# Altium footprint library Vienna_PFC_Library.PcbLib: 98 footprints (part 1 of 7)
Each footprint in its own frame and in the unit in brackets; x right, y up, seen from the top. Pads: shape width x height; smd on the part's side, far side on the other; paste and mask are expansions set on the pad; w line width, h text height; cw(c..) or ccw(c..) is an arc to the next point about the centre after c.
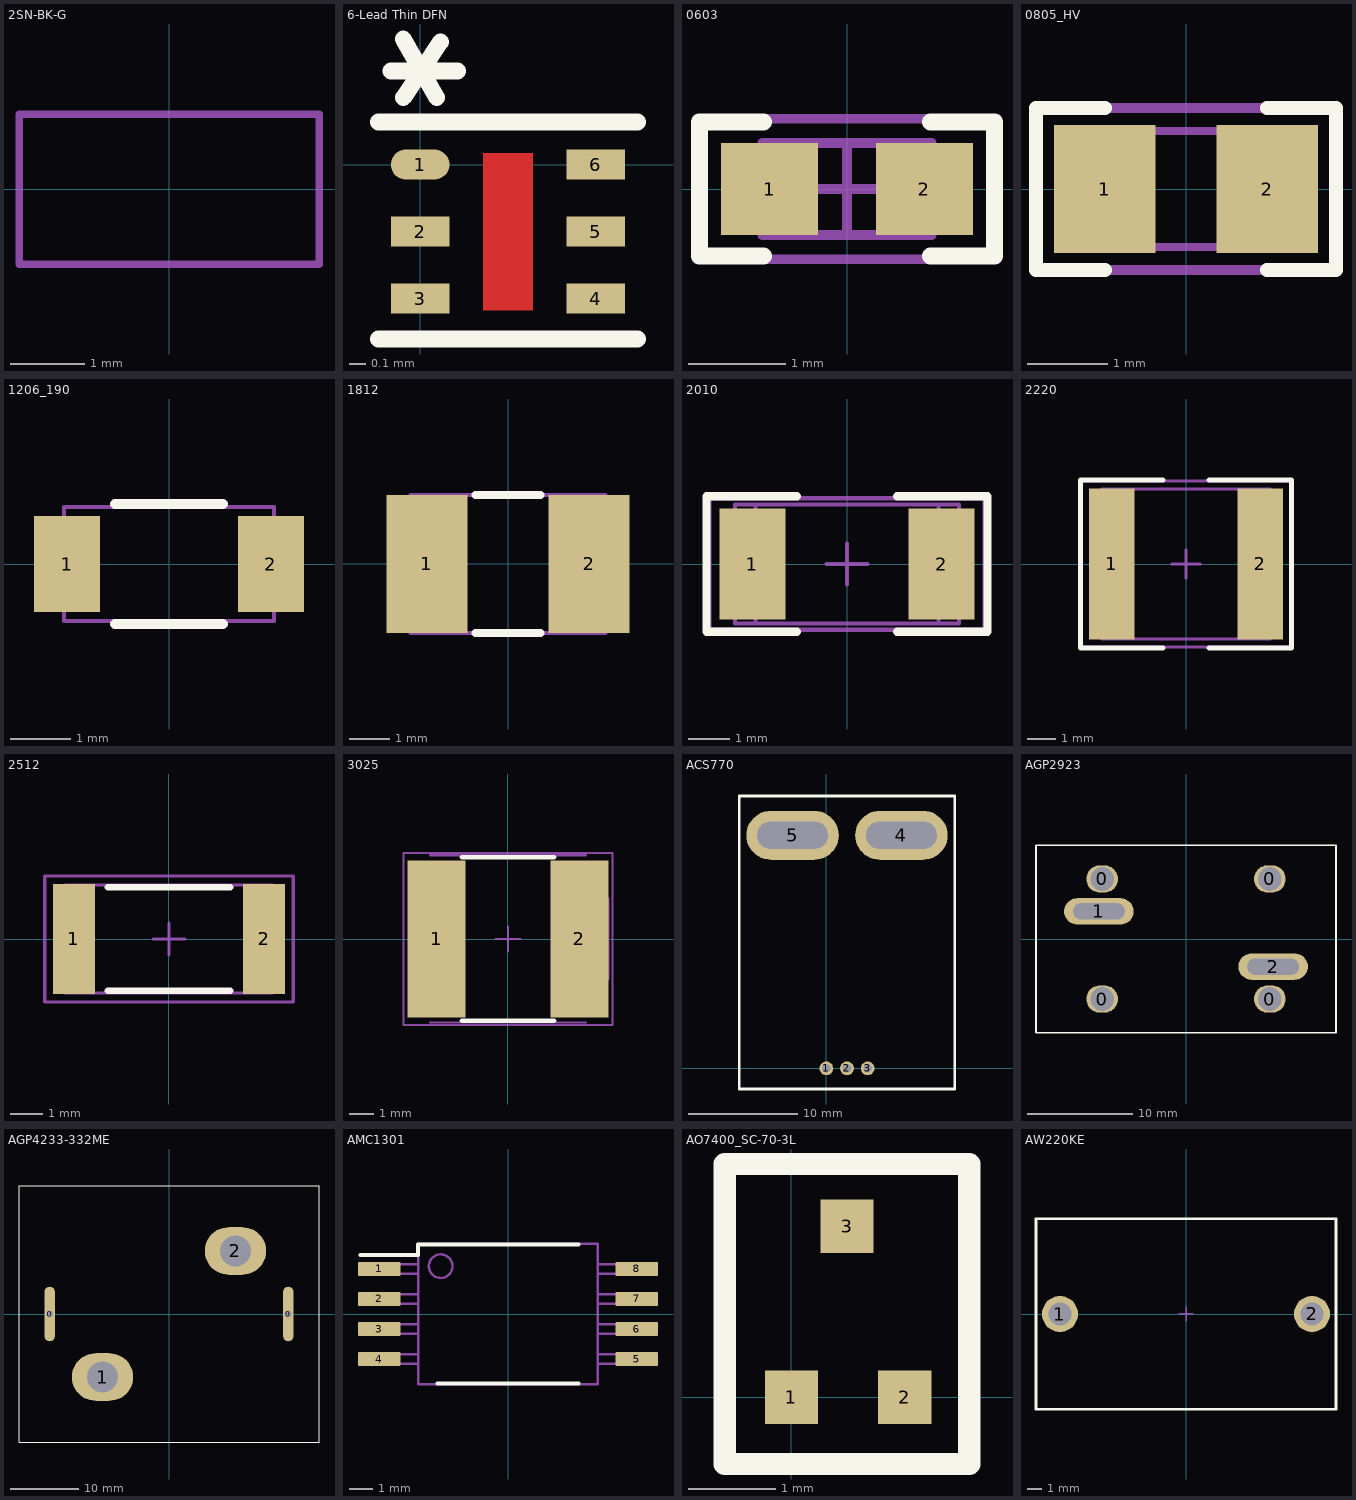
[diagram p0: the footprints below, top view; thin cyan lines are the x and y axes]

## 2SN-BK-G [mil] "Samtec STEP model"
height 345
pads (1):
  round 1 on Mech3: 0(0,0)
Mechanical 5:
  lines w4: -80,-40 80,-40 80,40 -80,40 -80,-40
3D body "2SN-BK-X-BASIC.stp": height 187.5, standoff 12.5, extent -78.5,-39.2 78.5,39.2

## 6-Lead Thin DFN [mm]
height 0.55
pads (6):
  oval 0.35x0.18 smd: 1(0,0)
  rect 0.35x0.18 smd: 2(0,-0.4) 3(0,-0.8) 4(1.05,-0.8) 5(1.05,-0.4) 6(1.05,0)
Top Layer:
  rectangle: 0.375,-0.87 0.675,0.07
Top Overlay:
  lines w0.1: -0.25,-1.041 1.3,-1.041 ; -0.25,0.254 1.3,0.254 ; -0.175,0.559 0.225,0.559 ; -0.1,0.4 0.122,0.733 ; -0.1,0.75 0.1,0.4

## 0603 [mm] "0603 from SM-752 data"
height 1
pads (2):
  rect 1x0.95 smd: 1(-0.8,0) 2(0.8,0)
Top Overlay:
  lines w0.178: -0.864,-0.691 -1.524,-0.691 -1.524,0.693 -0.864,0.693 ; 0.864,-0.691 1.524,-0.691 1.524,0.693 0.864,0.693
Mechanical 5:
  lines w0.1: -1.55,-0.725 -1.55,0.725 1.55,0.725 1.55,-0.725 -1.55,-0.725
Mechanical 13:
  lines w0.1: -0.55,-0.475 -0.55,0.475 ; 0.55,-0.475 0.55,0.475 ; -0.875,-0.475 0.875,-0.475 0.875,0.475 -0.875,0.475 -0.875,-0.475
Mechanical 15:
  lines w0.1: -0.475,0 0.475,0 ; 0,-0.475 0,0.475 ; -1.55,-0.725 1.55,-0.725 1.55,0.725 -1.55,0.725 -1.55,-0.725
3D body: height 1, standoff 0, extent -0.874,-0.474 -0.551,0.474
3D body: height 1, standoff 0, extent -0.549,-0.474 0.549,0.474
3D body: height 1, standoff 0, extent 0.551,-0.474 0.874,0.474

## 0805_HV [mil] "0805 with 30mil clearance between pads"
height 57.09
pads (2):
  rect 50x63 smd: 1(-40,0) 2(40,0)
Top Overlay:
  lines w7: -40,-40 -74,-40 -74,0 -74,40 -40,40 ; 40,-40 74,-40 74,0 74,40 40,40
Mechanical 5:
  lines w5: -74,-40 74,-40 74,40 -74,40 -74,-40
Mechanical 13:
  lines w3.94: -25.59,-28.54 -25.59,28.54 ; 25.59,-28.54 25.59,28.54 ; -43.31,-28.54 43.31,-28.54 43.31,28.54 -43.31,28.54 -43.31,-28.54
3D body: height 57.09, standoff 0, extent -43.29,-28.52 -25.61,28.52
3D body: height 57.09, standoff 0, extent -25.57,-28.52 25.57,28.52
3D body: height 57.09, standoff 0, extent 25.61,-28.52 43.29,28.52

## 1206_190 [mm] "1206_190"
height 1.9
pads (2):
  rect 1.1x1.6 smd: 1(-1.7,0) 2(1.7,0)
Top Overlay:
  lines w0.17: -0.9,-1 0.9,-1 ; -0.9,1 0.9,1
Mechanical 5:
  lines w0.07: -1.75,-0.95 -1.75,0.95 1.75,0.95 1.75,-0.95 -1.75,-0.95
3D body: height 1.9, standoff 0, extent 1.301,-0.949 1.749,0.949
3D body: height 1.9, standoff 0, extent -1.299,-0.949 1.299,0.949
3D body: height 1.9, standoff 0, extent -1.749,-0.949 -1.301,0.949

## 1812 [mm] "SMD, 2-Leads, Body 4.8x3.4mm"
height 2.54
pads (2):
  rect 2x3.4 smd: 1(-2,0) 2(2,0)
Top Overlay:
  lines w0.2: -0.8,-1.7 0.8,-1.7 ; -0.8,1.7 0.8,1.7
Mechanical 5:
  lines w0.1: -1.9,-1.7 -1.9,1.7 ; 1.9,-1.7 1.9,1.7 ; -2.4,-1.7 2.4,-1.7 2.4,1.7 -2.4,1.7 -2.4,-1.7
  text ".Designator" at -1.875,-0.5 h1.02
3D body: height 2.54, standoff 0, extent -2.399,-1.699 -1.901,1.699
3D body: height 2.54, standoff 0, extent -1.899,-1.699 1.899,1.699
3D body: height 2.54, standoff 0, extent 1.901,-1.699 2.399,1.699

## 2010 [mm] "Chip Capacitor, Body 5.08x2.54mm, IPC Medium Density"
height 1.66
pads (2):
  rect 1.6x2.7 smd: 1(-2.3,0) 2(2.3,0)
Top Overlay:
  lines w0.2: -1.219,-1.65 -3.419,-1.65 -3.419,1.65 -1.219,1.65 ; 1.219,-1.65 3.419,-1.65 3.419,1.65 1.219,1.65
Mechanical 5:
  lines w0.1: -2.73,-1.45 2.73,-1.45 2.73,1.45 -2.73,1.45 -2.73,-1.45
Mechanical 13:
  lines w0.1: -2.23,-1.45 -2.23,1.45 ; 2.23,-1.45 2.23,1.45 ; -2.73,-1.45 -2.73,1.45 2.73,1.45 2.73,-1.45 -2.73,-1.45
Mechanical 15:
  lines w0.1: -0.5,0 0.5,0 ; 0,-0.5 0,0.5 ; -3.35,-1.6 -3.35,1.6 3.35,1.6 3.35,-1.6 -3.35,-1.6
3D body: height 1.66, standoff 0, extent 2.231,-1.449 2.729,1.449
3D body: height 1.66, standoff 0, extent -2.229,-1.449 2.229,1.449
3D body: height 1.66, standoff 0, extent -2.729,-1.449 -2.231,1.449

## 2220 [mm] "Chip Capacitor, Body 5.7x5.0mm, IPC Medium Density"
height 2.8
pads (2):
  rect 1.6x5.3 smd: 1(-2.6,0) 2(2.6,0)
Top Overlay:
  lines w0.178: -0.811,-2.939 -3.693,-2.939 -3.693,2.939 -0.811,2.939 ; 0.811,-2.939 3.693,-2.939 3.693,2.939 0.811,2.939
Mechanical 5:
  lines w0.1: -2.95,-2.625 -2.95,2.625 2.95,2.625 2.95,-2.625 -2.95,-2.625
  text ".Designator" at -1.875,-0.5 h1.02
Mechanical 13:
  lines w0.1: -2.75,-2.625 -2.75,2.625 ; 2.75,-2.625 2.75,2.625 ; -2.95,-2.625 2.95,-2.625 2.95,2.625 -2.95,2.625 -2.95,-2.625
Mechanical 15:
  lines w0.1: -0.5,0 0.5,0 ; 0,-0.5 0,0.5 ; -3.65,-2.9 3.65,-2.9 3.65,2.9 -3.65,2.9 -3.65,-2.9
3D body: height 2.8, standoff 0, extent 2.751,-2.624 2.949,2.624
3D body: height 2.8, standoff 0, extent -2.749,-2.624 2.749,2.624
3D body: height 2.8, standoff 0, extent -2.949,-2.624 -2.751,2.624

## 2512 [mm] "Chip Resistor, Body 6.3x3.2mm, IPC Medium Density"
height 0.71
pads (2):
  rect 1.3x3.4 smd: 1(-2.95,0) 2(2.95,0)
Top Overlay:
  lines w0.2: -1.9,-1.6 1.9,-1.6 ; -1.9,1.6 1.9,1.6
Mechanical 5:
  lines w0.1: -3.225,-1.675 -3.225,1.675 3.225,1.675 3.225,-1.675 -3.225,-1.675
  text ".Designator" at -1.85,-0.5 h1.02
Mechanical 13:
  lines w0.1: -2.463,-1.675 -2.463,1.675 ; 2.463,-1.675 2.463,1.675 ; -3.225,-1.675 -3.225,1.675 3.225,1.675 3.225,-1.675 -3.225,-1.675
Mechanical 15:
  lines w0.1: -0.5,0 0.5,0 ; 0,-0.5 0,0.5 ; -3.85,-1.95 -3.85,1.95 3.85,1.95 3.85,-1.95 -3.85,-1.95
3D body: height 0.71, standoff 0, extent 2.464,-1.674 3.224,1.674
3D body: height 0.71, standoff 0, extent -2.462,-1.674 2.462,1.674
3D body: height 0.71, standoff 0, extent -3.224,-1.674 -2.464,1.674

## 3025 [mm] "Chip Resistor, Body 7.5*6.3mm, IPC Medium Density"
height 2.5
pads (2):
  rect 2.4x6.5 smd: 1(-2.95,0) 2(2.95,0)
Top Overlay:
  lines w0.2: -1.9,-3.378 1.9,-3.378 ; -1.9,3.378 1.9,3.378
Mechanical 5:
  lines w0.1: -3.987,-1.675 -3.987,1.675 ; -3.225,-3.453 3.225,-3.453 ; -3.225,3.453 3.225,3.453 ; 3.379,-1.675 3.379,1.675
Mechanical 13:
  lines w0.1: -3.987,-1.675 -3.987,1.675 ; -3.225,-3.453 3.225,-3.453 ; -3.225,-1.675 -3.225,1.675 ; -3.225,3.453 3.225,3.453 ; 3.379,-1.675 3.379,1.675 ; 4.141,-1.675 4.141,1.675
Mechanical 15:
  lines w0.1: -0.5,0 0.5,0 ; 0,-0.5 0,0.5 ; -4.318,-3.556 4.318,-3.556 4.318,3.556 -4.318,3.556 -4.318,-3.556
3D body: height 0.71, standoff 0, extent -3.986,-3.302 -3.226,3.302
3D body: height 0.71, standoff 0, extent -3.225,-3.302 3.302,3.302
3D body: height 0.71, standoff 0, extent 3.38,-3.302 4.14,3.302

## ACS770 [mm]
pads (5):
  round 1.27 hole 0.8: 1(0,0) 2(1.9,0) 3(3.8,0)
  oval 8.5x4.5 hole 2.5 slot 6.5 at 0 deg: 4(6.9,21.4) 5(-3.1,21.4)
Top Overlay:
  lines w0.254: -8,-1.9 -8,25 11.8,25 11.8,-1 11.8,-1.9 -7.9,-1.9
3D body: height 8.89, standoff 0, extent -8,-1.9 11.8,25

## AGP2923 [mm] "Inductor"
height 24
pads (6):
  oval 3x2.6 hole 2.24: 0(-7.95,-5.69) 0(-7.95,5.69) 0(7.95,-5.69) 0(7.95,5.69)
  oval 6.6x2.5 hole 1.54 slot 4.9 at 0 deg: 1(-8.26,2.62) 2(8.26,-2.62)
Top Overlay:
  lines w0.178: -14.224,-8.89 14.224,-8.89 14.224,8.89 -14.224,8.89 -14.224,-8.89
3D body "Coilcraft-AGP2923.STEP": height 24.45, standoff -3.1, extent -13.715,-8.485 13.715,8.485

## AGP4233-332ME [mm] "Inductor"
height 28
pads (4):
  oval 1.5x8 hole 1 square: 0(-17.5,0) 0(17.5,0)
  oval 9x7 hole 4.5 square: 1(-9.75,-9.25) 2(9.75,9.25)
Top Overlay:
  lines w0.178: -22,-18.8 22,-18.8 22,18.8 -22,18.8 -22,-18.8
3D body "Coilcraft-AGP4233_3_3-5_6uH.STEP": height 31.3, standoff -2, extent -21.6,-18.4 21.6,18.4

## AMC1301 [mm] "SOIC, 8-Leads, Body 5.95x7.6mm (max), Pitch 1.27mm"
height 2.8
pads (8):
  rrect17% 1.8x0.6 smd: 1(-5.45,1.905) 2(-5.45,0.635) 3(-5.45,-0.635) 4(-5.45,-1.905) 5(5.45,-1.905) 6(5.45,-0.635) 7(5.45,0.635) 8(5.45,1.905)
Top Overlay:
  lines w0.17: -6.25,2.5 -3.8,2.5 -3.8,2.95 2.975,2.95 ; -2.975,-2.95 2.975,-2.95
Mechanical 5:
  circle w0.1: c-2.85,2.025 r0.5
  lines w0.1: -3.805,-2.105 -5.8,-2.105 -5.8,-1.705 -3.805,-1.705 ; -3.805,-0.835 -5.8,-0.835 -5.8,-0.435 -3.805,-0.435 ; -3.805,0.435 -5.8,0.435 -5.8,0.835 -3.805,0.835 ; -3.805,1.705 -5.8,1.705 -5.8,2.105 -3.805,2.105 ; 3.805,-2.105 5.8,-2.105 5.8,-1.705 3.805,-1.705 ; 3.805,-0.835 5.8,-0.835 5.8,-0.435 3.805,-0.435 ; 3.805,0.435 5.8,0.435 5.8,0.835 3.805,0.835 ; 3.805,1.705 5.8,1.705 5.8,2.105 3.805,2.105 ; -3.8,-2.975 -3.8,2.975 3.8,2.975 3.8,-2.975 -3.8,-2.975
3D body "DWV0008A.stp": height 2.67, standoff -0.03, extent -5.768,-2.925 5.768,2.925

## AO7400_SC-70-3L [mil]
pads (3):
  rect 24x24 smd mask+4: 1(0,0) 2(51,0) 3(25,77)
Top Overlay:
  lines w10: -30,-30 80,-30 80,105 -30,105 -30,-30
3D body "SW3dPS-sot-3p290x130ll237h100.STEP": height 39.57, standoff 0, extent -27.09,-6.65 87.09,86.66

## AW220KE [mm] "Res"
pads (2):
  round 2.5 hole 1.6: 1(-8.75,0) 2(8.75,0)
Top Overlay:
  lines w0.178: -10.414,-6.604 10.414,-6.604 10.414,6.604 -10.414,6.604 -10.414,-6.604
Mechanical 15:
  lines w0.1: -0.5,0 0.5,0 ; 0,-0.5 0,0.5
3D body "AW220KE.stp": height 5.21, standoff -18.49, extent -10.033,-6.49 9.957,6.49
